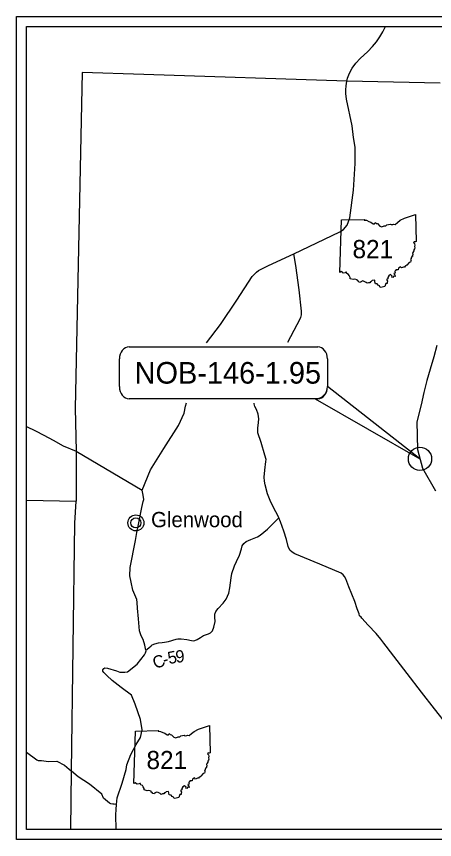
# Model space of a CAD drawing. Extents: x -452339 to 6403467, y -1 to 1814750.
# Drawn here: x -26129 to -5560, y 1588527 to 1629022 of the extents above; entities that cross this region are included whole.
import ezdxf

# ---------------------------------------------------------------- set-up
doc = ezdxf.new("R2010")
doc.units = 0
for name, color, linetype in [('Default', 7, 'Continuous'), ('GM_X_Adjacent_County_Text', 7, 'Continuous'), ('GM_X_County', 7, 'Continuous'), ('GM_X_County_Road', 7, 'Continuous'), ('GM_X_County_Road_Text', 7, 'Continuous'), ('GM_X_Section_Text', 7, 'Continuous'), ('GM_X_Township_ROW', 7, 'Continuous')]:
    doc.layers.add(name, color=color, linetype=linetype)

msp = doc.modelspace()

# ---------------------------------------------------------------- linework, layer by layer
at = {"layer": 'Default'}
for p, q in [((-25629, 1589027), (-25629, 1628522)), ((-25629, 1628522), (13866, 1628522)), ((-10227, 1616432), (-10144, 1619014)), ((-20362, 1591285), (-20279, 1593867)), ((13866, 1589027), (-25629, 1589027))]:
    msp.add_line(p, q, dxfattribs=at)
msp.add_lwpolyline([(14366, 1588527), (-26129, 1588527), (-26129, 1629022), (14366, 1629022)], close=True, dxfattribs=at)
for points in [[(-10144, 1619014), (-8999, 1619031), (-9016, 1619000), (-8909, 1618993), (-8794, 1618938), (-8697, 1618904), (-8579, 1618822), (-8507, 1618822), (-8477, 1618890), (-8423, 1618838), (-8358, 1618828), (-8246, 1618705), (-8154, 1618678), (-8044, 1618721), (-7962, 1618727), (-7901, 1618769), (-7744, 1618805), (-7700, 1618783), (-7617, 1618788), (-7575, 1618804), (-7502, 1618790), (-7375, 1618884), (-7244, 1618994), (-7041, 1619099), (-6740, 1619197), (-6500, 1619286), (-6466, 1617946)], [(-6466, 1617946), (-6501, 1617927), (-6556, 1617936), (-6593, 1617899), (-6547, 1617836), (-6526, 1617770), (-6545, 1617697), (-6526, 1617636), (-6538, 1617586), (-6573, 1617535), (-6585, 1617488), (-6614, 1617437), (-6612, 1617409), (-6640, 1617388), (-6635, 1617303), (-6649, 1617257), (-6644, 1617217), (-6690, 1617206), (-6679, 1617173), (-6708, 1617147), (-6702, 1617104), (-6735, 1617075), (-6703, 1617019), (-6728, 1617001), (-6750, 1616933), (-6808, 1616919), (-6923, 1616794), (-6965, 1616747), (-7011, 1616735), (-7037, 1616687), (-7093, 1616687), (-7180, 1616653), (-7235, 1616711), (-7332, 1616641), (-7344, 1616560), (-7466, 1616563), (-7462, 1616522), (-7489, 1616510), (-7514, 1616470), (-7500, 1616397), (-7558, 1616379), (-7551, 1616337), (-7513, 1616311), (-7497, 1616231), (-7558, 1616247), (-7608, 1616179), (-7661, 1616195), (-7644, 1616252), (-7731, 1616322), (-7813, 1616266), (-7856, 1616178), (-7857, 1616118), (-7919, 1616082), (-7879, 1615999), (-7887, 1615941), (-7885, 1615885), (-7962, 1615888), (-8009, 1615739)], [(-12770, 1613000), (-12317, 1613863), (-12146, 1614213), (-12108, 1614345), (-12106, 1614529), (-12216, 1615571), (-12379, 1616762), (-12486, 1617349)], [(-8009, 1615739), (-8142, 1615711), (-8234, 1615694), (-8267, 1615761), (-8334, 1615797), (-8377, 1615864), (-8472, 1615873), (-8495, 1615967), (-8505, 1616042), (-8636, 1616024), (-8671, 1615978), (-8717, 1615965), (-8744, 1615918), (-8807, 1615915), (-8875, 1615893), (-8919, 1615938), (-9030, 1615984), (-9080, 1616008), (-9184, 1615971), (-9206, 1615928), (-9288, 1615947), (-9308, 1615995), (-9358, 1616010), (-9369, 1616061), (-9476, 1616089), (-9559, 1616078), (-9703, 1616119), (-9712, 1616187), (-9761, 1616270), (-9786, 1616327), (-9877, 1616370), (-9896, 1616438), (-9925, 1616436), (-9952, 1616409), (-10054, 1616396), (-10094, 1616424), (-10151, 1616472), (-10227, 1616432)], [(-13222, 1604348), (-13247, 1604435), (-13364, 1604647), (-13611, 1605133), (-13774, 1605529), (-13885, 1605972), (-13922, 1606156), (-13940, 1606356), (-13910, 1606697), (-13853, 1607130), (-13850, 1607218), (-13903, 1607446), (-14096, 1608065), (-14133, 1608205), (-14198, 1608393), (-14255, 1608545), (-14260, 1608657), (-14257, 1608773), (-14223, 1609053), (-14204, 1609226), (-14213, 1609338), (-14237, 1609454), (-14319, 1609677), (-14404, 1609833), (-14428, 1609956), (-14433, 1609992)], [(-19759, 1597846), (-19614, 1597957), (-19507, 1598058), (-19451, 1598102), (-19328, 1598151), (-19144, 1598201), (-18956, 1598214), (-18844, 1598231), (-18649, 1598269), (-18274, 1598384), (-18186, 1598401), (-18030, 1598402), (-17750, 1598368), (-17518, 1598314), (-17434, 1598306), (-17354, 1598315), (-17230, 1598368), (-17075, 1598470), (-16920, 1598559), (-16688, 1598649), (-16589, 1598698), (-16489, 1598795), (-16415, 1598975), (-16357, 1599248), (-16374, 1599464), (-16367, 1599617), (-16320, 1599749), (-16201, 1599890), (-15963, 1600160), (-15805, 1600354), (-15675, 1600647), (-15625, 1600904), (-15572, 1601405), (-15530, 1601618), (-15401, 1601999), (-15298, 1602212), (-15152, 1602514), (-15059, 1602835), (-15024, 1602983), (-14948, 1603096), (-14833, 1603189), (-14594, 1603287), (-14267, 1603426), (-14136, 1603499), (-13786, 1603794), (-13222, 1604348)], [(-4886, 1594105), (-5564, 1594960), (-6197, 1595781), (-6899, 1596700), (-7730, 1597755), (-7944, 1598046), (-8053, 1598189), (-8199, 1598392), (-8425, 1598667), (-8827, 1599080), (-9141, 1599418), (-9174, 1599462), (-9246, 1599533), (-9271, 1599625), (-9373, 1599881), (-9487, 1600236), (-9772, 1600963), (-9931, 1601358), (-9987, 1601466), (-10052, 1601557), (-10156, 1601629), (-11207, 1602077), (-12426, 1602588), (-12559, 1602663), (-12675, 1602758), (-12760, 1602937), (-12847, 1603281), (-12970, 1603693), (-13141, 1604156), (-13222, 1604348)], [(-20279, 1593867), (-19134, 1593884), (-19152, 1593852), (-19044, 1593846), (-18930, 1593791), (-18832, 1593756), (-18714, 1593674), (-18643, 1593675), (-18613, 1593743), (-18559, 1593690), (-18494, 1593681), (-18382, 1593557), (-18290, 1593531), (-18179, 1593573), (-18098, 1593580), (-18037, 1593622), (-17880, 1593658), (-17836, 1593636), (-17753, 1593641), (-17710, 1593657), (-17638, 1593642), (-17511, 1593737), (-17379, 1593847), (-17177, 1593952), (-16875, 1594050), (-16636, 1594139), (-16602, 1592798)], [(-25629, 1592820), (-25126, 1592455), (-25057, 1592416), (-24893, 1592415), (-24549, 1592374), (-24149, 1592376), (-23762, 1592190), (-23415, 1591885)], [(-16602, 1592798), (-16637, 1592780), (-16692, 1592789), (-16728, 1592752), (-16682, 1592689), (-16661, 1592622), (-16680, 1592550), (-16661, 1592489), (-16674, 1592439), (-16709, 1592388), (-16720, 1592341), (-16750, 1592290), (-16748, 1592262), (-16775, 1592240), (-16770, 1592156), (-16785, 1592110), (-16780, 1592070), (-16825, 1592059), (-16815, 1592026), (-16844, 1592000), (-16837, 1591956), (-16870, 1591928), (-16839, 1591872), (-16864, 1591854), (-16885, 1591786), (-16944, 1591772), (-17059, 1591647), (-17101, 1591600), (-17146, 1591588), (-17172, 1591539), (-17229, 1591539), (-17315, 1591505), (-17371, 1591563), (-17468, 1591494), (-17479, 1591413), (-17602, 1591416), (-17598, 1591375), (-17625, 1591363), (-17650, 1591323), (-17636, 1591250), (-17693, 1591231), (-17686, 1591189), (-17649, 1591164), (-17633, 1591084), (-17694, 1591100), (-17744, 1591032), (-17796, 1591048), (-17779, 1591105), (-17867, 1591175), (-17949, 1591119), (-17992, 1591031), (-17993, 1590971), (-18055, 1590935), (-18014, 1590851), (-18022, 1590793), (-18021, 1590738), (-18098, 1590740), (-18145, 1590592)], [(-21207, 1590250), (-21318, 1590269), (-21384, 1590275), (-21487, 1590288), (-21556, 1590320), (-21849, 1590558), (-21930, 1590757), (-22539, 1591249), (-23087, 1591613), (-23415, 1591885)], [(-18145, 1590592), (-18278, 1590564), (-18370, 1590547), (-18403, 1590614), (-18469, 1590650), (-18513, 1590717), (-18608, 1590726), (-18630, 1590820), (-18641, 1590895), (-18771, 1590877), (-18806, 1590830), (-18853, 1590818), (-18880, 1590771), (-18943, 1590768), (-19011, 1590745), (-19055, 1590791), (-19165, 1590837), (-19215, 1590861), (-19320, 1590824), (-19341, 1590780), (-19424, 1590800), (-19444, 1590848), (-19494, 1590863), (-19505, 1590914), (-19612, 1590942), (-19694, 1590931), (-19838, 1590972), (-19848, 1591040), (-19897, 1591122), (-19922, 1591180), (-20013, 1591223), (-20032, 1591291), (-20061, 1591289), (-20088, 1591262), (-20190, 1591249), (-20230, 1591276), (-20287, 1591324), (-20362, 1591285)]]:
    msp.add_lwpolyline(points, dxfattribs=at)
at = {"layer": 'GM_X_County_Road'}
for points in [[(-9874, 1625832), (-9835, 1625992), (-9740, 1626233), (-9620, 1626478), (-9440, 1626729), (-9224, 1626959), (-8839, 1627295), (-8618, 1627536), (-8418, 1627776), (-8248, 1628017), (-8101, 1628271), (-7979, 1628522)], [(-16772, 1612962), (-16091, 1613869), (-15287, 1615056), (-14536, 1616230), (-14319, 1616440), (-14218, 1616519), (-13721, 1616766), (-12486, 1617349), (-10219, 1618418), (-10044, 1618537), (-9863, 1618759), (-9727, 1619109), (-9548, 1620483), (-9457, 1621787), (-9473, 1622594), (-9539, 1623071), (-9620, 1623646), (-9893, 1624951), (-9926, 1625230), (-9929, 1625418), (-9915, 1625602), (-9874, 1625832)], [(-5452, 1612834), (-5598, 1612271), (-5767, 1611676), (-5936, 1611118), (-6093, 1610515), (-6210, 1609909), (-6435, 1609083), (-6400, 1607721), (-6152, 1606793), (-5517, 1605679)], [(-19941, 1605711), (-19527, 1606723), (-18882, 1607761), (-18161, 1608903), (-17871, 1609510), (-17816, 1609855), (-17771, 1610013)], [(-25629, 1608846), (-25197, 1608631), (-24788, 1608421), (-24326, 1608175), (-23828, 1607905), (-23186, 1607629)], [(-23186, 1607629), (-19941, 1605711)], [(-21222, 1589027), (-21234, 1589736), (-21229, 1590013), (-21207, 1590250), (-21177, 1590578), (-20923, 1591301), (-20730, 1591980), (-20702, 1592195), (-20500, 1592707), (-20239, 1593210), (-20034, 1593547), (-19948, 1593924), (-20026, 1594437), (-20281, 1595193), (-20475, 1595629), (-20977, 1596012), (-21427, 1596350), (-21689, 1596606), (-21830, 1596749), (-21877, 1596814), (-21881, 1596878), (-21838, 1596942), (-21778, 1596967), (-21650, 1596963), (-21213, 1596825), (-21044, 1596765), (-20793, 1596754), (-20673, 1596771), (-20197, 1597163), (-19828, 1597611), (-19772, 1597715), (-19753, 1597812), (-19759, 1597846), (-19807, 1598094), (-19896, 1598370), (-19993, 1598546), (-20082, 1598799), (-20121, 1599380), (-20171, 1599917), (-20192, 1600193), (-20212, 1600341), (-20402, 1600802), (-20492, 1601198), (-20549, 1601506), (-20531, 1601915), (-20275, 1603232), (-20185, 1603737), (-20141, 1603952), (-19953, 1604865), (-19892, 1605156), (-19870, 1605262), (-19903, 1605474), (-19941, 1605711)]]:
    msp.add_lwpolyline(points, dxfattribs=at)
at = {"layer": 'GM_X_County_Road_Text'}
for radius in [393, 249]:
    msp.add_circle((-20253, 1604104), radius, dxfattribs=at)
at = {"layer": 'GM_X_Section_Text'}
for p, q in [((-22890, 1626269), (-23233, 1609748)), ((-19858, 1626167), (-22890, 1626269)), ((-9874, 1625832), (-19858, 1626167)), ((-5283, 1625736), (-9874, 1625832)), ((-23233, 1609748), (-23186, 1607629)), ((-23186, 1607629), (-23199, 1605167)), ((-25629, 1605231), (-23199, 1605167)), ((-23249, 1604100), (-23199, 1605167)), ((-23249, 1604100), (-23199, 1605167)), ((-23415, 1591885), (-23249, 1604100)), ((-23453, 1589027), (-23415, 1591885))]:
    msp.add_line(p, q, dxfattribs=at)
at = {"layer": 'GM_X_Township_ROW'}
for p, q in [((-6276, 1607257), (-10825, 1610810)), ((-11425, 1610210), (-6276, 1607257))]:
    msp.add_line(p, q, dxfattribs=at)
for points in [[(-20585, 1612770), (-11305, 1612770)], [(-21065, 1610810), (-21065, 1612170)], [(-10825, 1612170), (-10825, 1610810)], [(-11305, 1610210), (-20585, 1610210)]]:
    msp.add_lwpolyline(points, dxfattribs=at)
msp.add_circle((-6276, 1607257), 572, dxfattribs=at)
msp.add_arc((-11425, 1610810), 600, 270, 0, dxfattribs=at)
for centre, major_axis, start_param, end_param in [((-20585, 1612170), (0, -600), 3.141593, 4.712389), ((-11305, 1612170), (0, 600), 4.712389, 6.283185), ((-20585, 1610810), (0, -600), 4.712389, 6.283185), ((-11305, 1610810), (0, 600), 3.141593, 4.712389)]:
    msp.add_ellipse(centre, major_axis=major_axis, ratio=0.8, start_param=start_param, end_param=end_param, dxfattribs=at)

# ---------------------------------------------------------------- texts
at = {"layer": 'Default'}
for p in [(-9596, 1617129), (-19732, 1591992)]:
    msp.add_text('821', height=895.5, dxfattribs=at).set_placement(p)
at = {"layer": 'GM_X_Adjacent_County_Text'}
msp.add_text('Glenwood', height=750, rotation=0, dxfattribs=at).set_placement((-19506, 1603894))
at = {"layer": 'GM_X_County'}
for s, rotation, p in [('C', 21.1349, (-19293, 1596906)), ('5', 11.5896, (-18625, 1597152)), ('9', 5.2261, (-18280, 1597224)), ('-', 17.9532, (-18842, 1597080))]:
    msp.add_text(s, height=600, rotation=rotation, dxfattribs=at).set_placement(p)
at = {"layer": 'GM_X_Township_ROW'}
msp.add_text('NOB-146-1.95', height=1063.82, dxfattribs=at).set_placement((-20315, 1610958))

doc.saveas('drawing.dxf')
